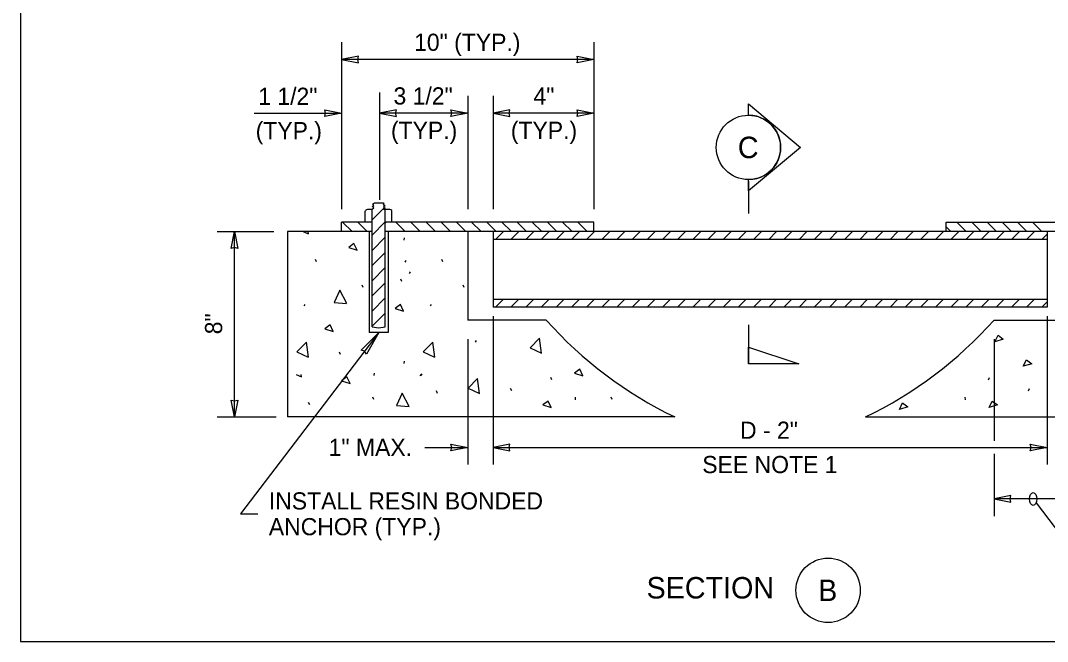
# Model space of a CAD drawing. Extents: x 99862 to 103151, y 100000 to 102076.
# Drawn here: x 99862 to 100819, y 100000 to 100578 of the extents above; entities that cross this region are included whole.
import ezdxf

# ---------------------------------------------------------------- set-up
doc = ezdxf.new("R2010")
doc.units = 0
for name, color, linetype in [('Level 1', 7, 'Continuous'), ('Level 13', 7, 'Continuous'), ('Level 15', 7, 'Continuous'), ('Level 17', 7, 'Continuous'), ('Level 18', 7, 'Continuous'), ('Level 20', 7, 'Continuous'), ('Level 60', 7, 'Continuous'), ('Level 9', 7, 'Continuous')]:
    doc.layers.add(name, color=color, linetype=linetype)

msp = doc.modelspace()

# ---------------------------------------------------------------- linework, layer by layer
at = {"layer": 'Level 1'}
for p, q in [((100189.8, 100404.96), (100191.18, 100405.86)), ((100190.07, 100406.97), (100191.87, 100408.35)), ((100191.18, 100405.86), (100190.07, 100406.97)), ((100191.87, 100408.35), (100200.04, 100408.21)), ((100200.04, 100408.21), (100200.73, 100407.45)), ((100200.73, 100407.45), (100200.04, 100406.97)), ((100200.04, 100406.97), (100201.97, 100405.45)), ((100201.97, 100405.45), (100200.45, 100404.61)), ((100183.09, 100390.29), (100183.09, 100400.12)), ((100189.94, 100402.12), (100185.3, 100402.12)), ((100189.69, 100292.7), (100189.69, 100402.12)), ((100189.73, 100402.33), (100191.32, 100403.51)), ((100189.94, 100402.12), (100189.73, 100402.33)), ((100191.32, 100403.51), (100189.8, 100404.96)), ((100201.97, 100403.16), (100200.42, 100402.12)), ((100206.19, 100402.12), (100200.42, 100402.12)), ((100200.45, 100404.61), (100201.97, 100403.16)), ((100201.97, 100292.7), (100201.97, 100402.12)), ((100208.2, 100390.29), (100208.2, 100401.01)), ((100161.32, 100381.51), (100161.32, 100390.29)), ((100189.69, 100390.29), (100161.32, 100390.29)), ((100189.69, 100381.51), (100189.69, 100390.29)), ((100396.55, 100390.29), (100201.97, 100390.29)), ((100396.55, 100381.51), (100396.55, 100390.29)), ((100724.89, 100381.51), (100724.89, 100390.29)), ((100724.89, 100390.29), (100919.47, 100390.29)), ((100187.04, 100381.46), (100187.04, 100287.3)), ((100204.68, 100381.46), (100204.68, 100287.3)), ((100842.5, 100381.51), (100278.94, 100381.51)), ((100302.46, 100381.51), (100302.46, 100310.94)), ((100818.98, 100381.51), (100818.98, 100310.94)), ((100818.98, 100374.1), (100302.46, 100374.1)), ((100818.98, 100318.27), (100302.46, 100318.27)), ((100818.98, 100310.94), (100302.46, 100310.94)), ((100204.68, 100287.3), (100187.04, 100287.3))]:
    msp.add_line(p, q, dxfattribs=at)
msp.add_lwpolyline([(99862, 99999.5), (103151, 99999.5), (103151, 102075.5), (99862, 102075.5)], close=True, dxfattribs=at)
msp.add_lwpolyline([(100189.69, 100292.7), (100195.83, 100291.73), (100201.97, 100292.7)], dxfattribs=at)
for centre, radius, start, end in [((100186.75, 100398.22), 4.13, 110.20557, 152.52832), ((100206.21, 100399.77), 2.33, 32.69635, 91.70415)]:
    msp.add_arc(centre, radius, start, end, dxfattribs=at)
at = {"layer": 'Level 13'}
for p, q in [((100110.72, 100381.51), (100110.72, 100208.71)), ((100189.69, 100381.51), (100110.72, 100381.51)), ((100278.94, 100381.51), (100201.97, 100381.51)), ((100278.94, 100381.51), (100278.94, 100298.94)), ((100352.02, 100298.94), (100278.94, 100298.94)), ((100769.42, 100298.94), (100842.5, 100298.94)), ((100471.79, 100208.71), (100110.72, 100208.71)), ((100649.65, 100208.71), (101010.73, 100208.71))]:
    msp.add_line(p, q, dxfattribs=at)
for centre, start, end in [((100638.77, 100554.93), 221.7557, 244.2524), ((100482.67, 100554.93), 295.7476, 318.2443)]:
    msp.add_arc(centre, 384.39, start, end, dxfattribs=at)
at = {"layer": 'Level 15'}
for p, q in [((100161.32, 100557.88), (100161.32, 100402.28)), ((100396.55, 100557.88), (100396.55, 100402.28)), ((100396.48, 100541.88), (100161.32, 100541.88)), ((100196.61, 100510.91), (100196.61, 100411.05)), ((100278.93, 100507.87), (100278.93, 100402.28)), ((100302.46, 100507.87), (100302.46, 100402.28)), ((100079.7, 100491.88), (100161.32, 100491.88)), ((100278.93, 100491.88), (100196.61, 100491.88)), ((100396.55, 100491.88), (100302.46, 100491.88)), ((100045.4, 100381.51), (100098.07, 100381.51)), ((100061.4, 100208.71), (100061.4, 100381.51)), ((100302.46, 100302.64), (100302.46, 100164.37)), ((100818.98, 100302.64), (100818.98, 100164.37)), ((100195.86, 100287.3), (100067.1, 100118.47)), ((100278.94, 100281.16), (100278.94, 100164.37)), ((100769.42, 100281.16), (100769.42, 100186.37)), ((100045.4, 100208.71), (100100.21, 100208.71)), ((100238.95, 100180.37), (100278.94, 100180.37)), ((100302.46, 100180.37), (100818.98, 100180.37)), ((100769.42, 100174.37), (100769.42, 100116.31)), ((100842.5, 100132.31), (100769.42, 100132.31)), ((100808.72, 100128.67), (100837.27, 100090.94)), ((100067.1, 100118.47), (100083.1, 100118.47))]:
    msp.add_line(p, q, dxfattribs=at)
for points in [[(100161.32, 100541.88), (100177.05, 100538.8), (100176.32, 100541.88), (100177.05, 100544.97)], [(100396.48, 100541.88), (100380.76, 100538.8), (100381.49, 100541.88), (100380.76, 100544.97)], [(100161.32, 100491.88), (100145.6, 100488.8), (100146.33, 100491.88), (100145.6, 100494.97)], [(100196.61, 100491.88), (100212.34, 100488.8), (100211.61, 100491.88), (100212.34, 100494.97)], [(100278.93, 100491.88), (100263.21, 100488.8), (100263.94, 100491.88), (100263.21, 100494.97)], [(100302.46, 100491.88), (100318.19, 100488.8), (100317.46, 100491.88), (100318.19, 100494.97)], [(100396.55, 100491.88), (100380.83, 100488.8), (100381.56, 100491.88), (100380.83, 100494.97)], [(100061.4, 100381.51), (100064.48, 100365.79), (100061.4, 100366.52), (100058.31, 100365.79)], [(100195.86, 100287.3), (100184.39, 100267.34), (100182.66, 100269.99), (100179.64, 100270.96)], [(100061.4, 100208.71), (100058.31, 100224.43), (100061.4, 100223.7), (100064.48, 100224.43)], [(100278.94, 100180.37), (100263.22, 100177.29), (100263.95, 100180.37), (100263.22, 100183.46)], [(100302.46, 100180.37), (100318.19, 100177.29), (100317.46, 100180.37), (100318.19, 100183.46)], [(100818.98, 100180.37), (100803.26, 100177.29), (100803.99, 100180.37), (100803.26, 100183.46)], [(100769.42, 100132.31), (100785.15, 100129.23), (100784.42, 100132.31), (100785.15, 100135.39)]]:
    msp.add_lwpolyline(points, close=True, dxfattribs=at)
msp.add_ellipse((100805.96, 100132.31), major_axis=(0, -6), ratio=0.57735, dxfattribs=at)
at = {"layer": 'Level 17'}
for p, q in [((100219.64, 100375.56), (100219.37, 100373.34)), ((100138.01, 100353.21), (100136.97, 100355.42)), ((100221.1, 100354.39), (100220.13, 100352.93)), ((100255.69, 100353.21), (100254.72, 100355.42)), ((100225.32, 100343.87), (100224.35, 100342.42)), ((100181.38, 100329.34), (100180.42, 100331.55)), ((100217.36, 100335.01), (100216.39, 100337.23)), ((100275.61, 100329.34), (100274.64, 100331.55)), ((100127.15, 100313.64), (100126.17, 100312.18)), ((100244.9, 100313.64), (100243.93, 100312.18)), ((100286.67, 100279.86), (100285.71, 100278.4)), ((100160.36, 100266.94), (100159.38, 100269.15)), ((100219.64, 100260.78), (100219.37, 100258.57)), ((100191.54, 100249.51), (100191.32, 100247.29)), ((100235.21, 100248.34), (100234.25, 100246.88)), ((100236.18, 100248.89), (100235.21, 100247.44)), ((100357.17, 100243.26), (100356.2, 100245.47)), ((100764.28, 100243.26), (100765.25, 100245.47)), ((100319.81, 100233.16), (100318.84, 100235.37)), ((100801.64, 100233.16), (100802.61, 100235.37)), ((100191.21, 100225.02), (100190.24, 100227.23)), ((100250.71, 100230.69), (100249.67, 100232.91)), ((100379.11, 100227), (100378.89, 100224.79)), ((100413.64, 100225), (100412.67, 100227.21)), ((100742.34, 100227), (100742.56, 100224.79)), ((100131.54, 100220.08), (100130.57, 100222.29))]:
    msp.add_line(p, q, dxfattribs=at)
for points in [[(100125.42, 100381.51), (100130.19, 100379.29)], [(100130.47, 100379.22), (100130.12, 100381.51)], [(100175.78, 100364.15), (100172.8, 100370.3), (100167.89, 100366.57), (100175.78, 100364.15)], [(100166.27, 100314.36), (100159.63, 100326.89), (100154.44, 100315.4), (100165.99, 100314.36)], [(100219.09, 100307.27), (100216.11, 100313.36), (100211.21, 100309.69), (100219.09, 100307.27)], [(100153.45, 100288.35), (100150.54, 100294.44), (100145.63, 100290.77), (100153.45, 100288.35)], [(100347.7, 100268.19), (100345.77, 100282.23), (100336.98, 100273.17), (100347.5, 100268.26)], [(100770.26, 100278.81), (100773.16, 100284.9), (100778.08, 100281.23), (100770.26, 100278.81)], [(100130.47, 100264.38), (100128.53, 100278.42), (100119.67, 100269.36), (100130.19, 100264.45)], [(100248.15, 100264.38), (100246.21, 100278.42), (100237.43, 100269.36), (100247.94, 100264.45)], [(100796.72, 100255.92), (100799.7, 100262.01), (100804.61, 100258.34), (100796.72, 100255.92)], [(100386.21, 100247), (100383.31, 100253.09), (100378.39, 100249.42), (100386.21, 100247)], [(100119.01, 100248.38), (100123.79, 100246.16)], [(100123.99, 100246.09), (100123.65, 100248.38)], [(100169.12, 100239.96), (100166.21, 100246.12), (100161.3, 100242.38), (100169.12, 100239.96)], [(100289.92, 100230.6), (100287.99, 100244.64), (100279.2, 100235.58), (100289.72, 100230.67)], [(100224.35, 100218.38), (100217.71, 100230.9), (100212.59, 100219.42), (100224.14, 100218.38)], [(100356.69, 100217.45), (100353.78, 100223.54), (100348.87, 100219.87), (100356.69, 100217.45)], [(100764.76, 100217.45), (100767.67, 100223.54), (100772.58, 100219.87), (100764.76, 100217.45)], [(100681.29, 100215.62), (100684.27, 100221.77), (100689.18, 100218.04), (100681.29, 100215.62)]]:
    msp.add_lwpolyline(points, dxfattribs=at)
at = {"layer": 'Level 18'}
for p, q in [((100201.27, 100403.83), (100189.69, 100392.25)), ((100170.98, 100381.51), (100162.2, 100390.29)), ((100185.13, 100381.51), (100176.35, 100390.29)), ((100201.97, 100390.39), (100189.69, 100378.11)), ((100201.97, 100389.32), (100202.95, 100390.29)), ((100220.5, 100381.51), (100211.72, 100390.29)), ((100234.65, 100381.51), (100225.87, 100390.29)), ((100248.79, 100381.51), (100240.01, 100390.29)), ((100262.93, 100381.51), (100254.15, 100390.29)), ((100277.07, 100381.51), (100268.29, 100390.29)), ((100291.22, 100381.51), (100282.44, 100390.29)), ((100305.36, 100381.51), (100296.58, 100390.29)), ((100319.5, 100381.51), (100310.72, 100390.29)), ((100333.64, 100381.51), (100324.86, 100390.29)), ((100347.78, 100381.51), (100339, 100390.29)), ((100361.93, 100381.51), (100353.15, 100390.29)), ((100376.07, 100381.51), (100367.29, 100390.29)), ((100390.21, 100381.51), (100381.43, 100390.29)), ((100743.42, 100381.51), (100734.64, 100390.29)), ((100757.57, 100381.51), (100748.79, 100390.29)), ((100771.71, 100381.51), (100762.93, 100390.29)), ((100785.85, 100381.51), (100777.07, 100390.29)), ((100799.99, 100381.51), (100791.21, 100390.29)), ((100814.13, 100381.51), (100805.35, 100390.29)), ((100312.22, 100381.51), (100304.81, 100374.1)), ((100326.37, 100381.51), (100318.96, 100374.1)), ((100340.51, 100381.51), (100333.1, 100374.1)), ((100354.65, 100381.51), (100347.24, 100374.1)), ((100368.79, 100381.51), (100361.38, 100374.1)), ((100382.93, 100381.51), (100375.52, 100374.1)), ((100397.08, 100381.51), (100389.67, 100374.1)), ((100411.22, 100381.51), (100403.81, 100374.1)), ((100425.36, 100381.51), (100417.95, 100374.1)), ((100439.5, 100381.51), (100432.09, 100374.1)), ((100453.64, 100381.51), (100446.23, 100374.1)), ((100467.79, 100381.51), (100460.38, 100374.1)), ((100481.93, 100381.51), (100474.52, 100374.1)), ((100496.07, 100381.51), (100488.66, 100374.1)), ((100510.21, 100381.51), (100502.8, 100374.1)), ((100524.36, 100381.51), (100516.95, 100374.1)), ((100538.5, 100381.51), (100531.09, 100374.1)), ((100552.64, 100381.51), (100545.23, 100374.1)), ((100566.78, 100381.51), (100559.37, 100374.1)), ((100580.92, 100381.51), (100573.51, 100374.1)), ((100595.07, 100381.51), (100587.66, 100374.1)), ((100609.21, 100381.51), (100601.8, 100374.1)), ((100623.35, 100381.51), (100615.94, 100374.1)), ((100637.49, 100381.51), (100630.08, 100374.1)), ((100651.63, 100381.51), (100644.22, 100374.1)), ((100665.78, 100381.51), (100658.37, 100374.1)), ((100679.92, 100381.51), (100672.51, 100374.1)), ((100694.06, 100381.51), (100686.65, 100374.1)), ((100708.2, 100381.51), (100700.79, 100374.1)), ((100722.35, 100381.51), (100714.94, 100374.1)), ((100729.28, 100381.51), (100724.89, 100385.9)), ((100736.49, 100381.51), (100729.08, 100374.1)), ((100750.63, 100381.51), (100743.22, 100374.1)), ((100764.77, 100381.51), (100757.36, 100374.1)), ((100778.91, 100381.51), (100771.5, 100374.1)), ((100793.06, 100381.51), (100785.65, 100374.1)), ((100807.2, 100381.51), (100799.79, 100374.1)), ((100818.98, 100379.16), (100813.93, 100374.1)), ((100201.97, 100376.25), (100189.69, 100363.97)), ((100201.97, 100362.11), (100189.69, 100349.83)), ((100201.97, 100347.97), (100189.69, 100335.69)), ((100201.97, 100333.82), (100189.69, 100321.54)), ((100201.97, 100319.68), (100189.69, 100307.4)), ((100312.22, 100318.35), (100304.81, 100310.94)), ((100326.37, 100318.35), (100318.96, 100310.94)), ((100340.51, 100318.35), (100333.1, 100310.94)), ((100354.65, 100318.35), (100347.24, 100310.94)), ((100368.79, 100318.35), (100361.38, 100310.94)), ((100382.93, 100318.35), (100375.52, 100310.94)), ((100397.08, 100318.35), (100389.67, 100310.94)), ((100411.22, 100318.35), (100403.81, 100310.94)), ((100425.36, 100318.35), (100417.95, 100310.94)), ((100439.5, 100318.35), (100432.09, 100310.94)), ((100453.64, 100318.35), (100446.23, 100310.94)), ((100467.79, 100318.35), (100460.38, 100310.94)), ((100481.93, 100318.35), (100474.52, 100310.94)), ((100496.07, 100318.35), (100488.66, 100310.94)), ((100510.21, 100318.35), (100502.8, 100310.94)), ((100524.36, 100318.35), (100516.95, 100310.94)), ((100538.5, 100318.35), (100531.09, 100310.94)), ((100552.64, 100318.35), (100545.23, 100310.94)), ((100566.78, 100318.35), (100559.37, 100310.94)), ((100580.92, 100318.35), (100573.51, 100310.94)), ((100595.07, 100318.35), (100587.66, 100310.94)), ((100609.21, 100318.35), (100601.8, 100310.94)), ((100623.35, 100318.35), (100615.94, 100310.94)), ((100637.49, 100318.35), (100630.08, 100310.94)), ((100651.63, 100318.35), (100644.22, 100310.94)), ((100665.78, 100318.35), (100658.37, 100310.94)), ((100679.92, 100318.35), (100672.51, 100310.94)), ((100694.06, 100318.35), (100686.65, 100310.94)), ((100708.2, 100318.35), (100700.79, 100310.94)), ((100722.35, 100318.35), (100714.94, 100310.94)), ((100736.49, 100318.35), (100729.08, 100310.94)), ((100750.63, 100318.35), (100743.22, 100310.94)), ((100764.77, 100318.35), (100757.36, 100310.94)), ((100778.91, 100318.35), (100771.5, 100310.94)), ((100793.06, 100318.35), (100785.65, 100310.94)), ((100807.2, 100318.35), (100799.79, 100310.94)), ((100818.98, 100316), (100813.93, 100310.94)), ((100201.97, 100305.54), (100189.69, 100293.26))]:
    msp.add_line(p, q, dxfattribs=at)
at = {"layer": 'Level 20'}
msp.add_circle((100540.51, 100459.9), 30, dxfattribs=at)
at = {"layer": 'Level 60'}
msp.add_line((99862, 99999.5), (99862, 99999.5), dxfattribs=at)
at = {"layer": 'Level 9'}
for p, q in [((100540.51, 100489.9), (100540.51, 100500.5)), ((100540.51, 100500.5), (100588.97, 100459.9)), ((100588.97, 100459.9), (100540.51, 100419.3)), ((100540.51, 100419.3), (100540.51, 100429.9)), ((100540.51, 100428.33), (100540.51, 100398.33)), ((100540.51, 100294.61), (100540.51, 100258.09))]:
    msp.add_line(p, q, dxfattribs=at)
msp.add_lwpolyline([(100540.51, 100273.61), (100587.39, 100258.09), (100540.51, 100258.09)], close=True, dxfattribs=at)
msp.add_circle((100614.74, 100047.15), 30, dxfattribs=at)
msp.add_arc((100540.51, 100459.9), 30, 269.99779, 90.00221, dxfattribs=at)

# ---------------------------------------------------------------- texts
at = {"layer": 'Level 20'}
for s, height, p in [('10" (TYP.)', 16, (100228.85, 100549.88)), ('1 1/2"', 16, (100083.56, 100499.54)), ('3 1/2"', 16, (100209.68, 100499.88)), ('4"', 16, (100340.14, 100499.88)), ('(TYP.)', 16, (100081.16, 100467.54)), ('(TYP.)', 16, (100207.29, 100467.88)), ('(TYP.)', 16, (100319.02, 100467.88)), ('C', 20, (100530.62, 100449.88)), ('D - 2"', 16, (100532.66, 100188.37)), ('1" MAX.', 16, (100149.2, 100172.37)), ('SEE NOTE 1', 16, (100497.48, 100156.37)), ('INSTALL RESIN BONDED', 16, (100093.43, 100122.47)), ('ANCHOR (TYP.)', 16, (100093.43, 100098.47)), ('SECTION', 20, (100445.55, 100039.54)), ('B', 20, (100605.49, 100037.15))]:
    msp.add_text(s, height=height, dxfattribs=at).set_placement(p)
msp.add_text('8"', height=16, rotation=90, dxfattribs=at).set_placement((100049.95, 100285.75))

doc.saveas('drawing.dxf')
